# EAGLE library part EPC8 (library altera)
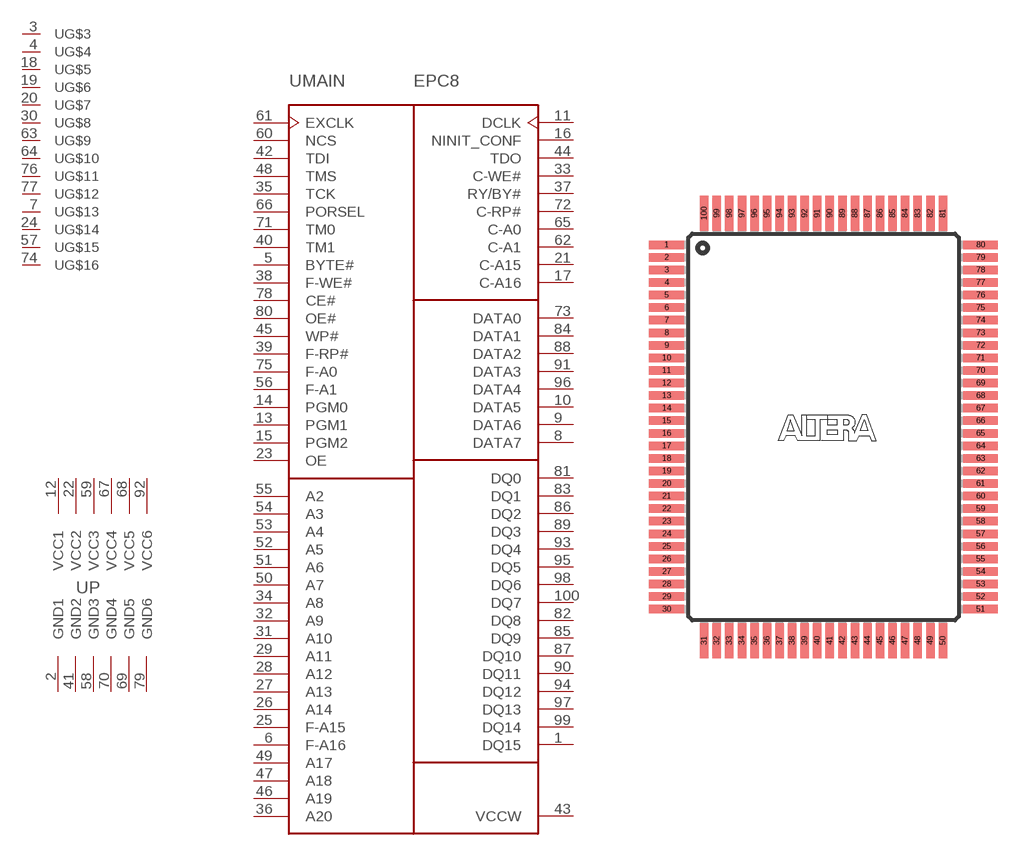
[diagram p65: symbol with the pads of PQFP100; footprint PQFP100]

Designator prefix -; gates MAIN=EPC8 P=EPC8_P G$3=NC G$4=NC G$5=NC G$6=NC G$7=NC G$8=NC G$9=NC G$10=NC G$11=NC G$12=NC G$13=NC G$14=NC G$15=NC G$16=NC

## EPC8  [PQFP100]
1  MAIN:DQ15
2  P:GND1  pwr
3  G$3:NC  nc
4  G$4:NC  nc
5  MAIN:BYTE#  in
6  MAIN:F-A16  in
7  G$13:NC  nc
8  MAIN:DATA7  out
9  MAIN:DATA6  out
10  MAIN:DATA5  out
11  MAIN:DCLK  out
12  P:VCC1  pwr
13  MAIN:PGM1  in
14  MAIN:PGM0  in
15  MAIN:PGM2  in
16  MAIN:NINIT_CONF  out
17  MAIN:C-A16  out
18  G$5:NC  nc
19  G$6:NC  nc
20  G$7:NC  nc
21  MAIN:C-A15  out
22  P:VCC2  pwr
23  MAIN:OE
24  G$14:NC  nc
25  MAIN:F-A15  in
26  MAIN:A14  in
27  MAIN:A13  in
28  MAIN:A12  in
29  MAIN:A11  in
30  G$8:NC  nc
31  MAIN:A10  in
32  MAIN:A9  in
33  MAIN:C-WE#  out
34  MAIN:A8  in
35  MAIN:TCK  in
36  MAIN:A20  in
37  MAIN:RY/BY#  out
38  MAIN:F-WE#  in
39  MAIN:F-RP#  in
40  MAIN:TM1  in
41  P:GND2  pwr
42  MAIN:TDI  in
43  MAIN:VCCW  pwr
44  MAIN:TDO  out
45  MAIN:WP#  in
46  MAIN:A19  in
47  MAIN:A18  in
48  MAIN:TMS  in
49  MAIN:A17  in
50  MAIN:A7  in
51  MAIN:A6  in
52  MAIN:A5  in
53  MAIN:A4  in
54  MAIN:A3  in
55  MAIN:A2  in
56  MAIN:F-A1  in
57  G$15:NC  nc
58  P:GND3  pwr
59  P:VCC3  pwr
60  MAIN:NCS  in
61  MAIN:EXCLK  in
62  MAIN:C-A1  out
63  G$9:NC  nc
64  G$10:NC  nc
65  MAIN:C-A0  out
66  MAIN:PORSEL  in
67  P:VCC4  pwr
68  P:VCC5  pwr
69  P:GND5  pwr
70  P:GND4  pwr
71  MAIN:TM0  in
72  MAIN:C-RP#  out
73  MAIN:DATA0  out
74  G$16:NC  nc
75  MAIN:F-A0  in
76  G$11:NC  nc
77  G$12:NC  nc
78  MAIN:CE#  in
79  P:GND6  pwr
80  MAIN:OE#  in
81  MAIN:DQ0
82  MAIN:DQ8
83  MAIN:DQ1
84  MAIN:DATA1  out
85  MAIN:DQ9
86  MAIN:DQ2
87  MAIN:DQ10
88  MAIN:DATA2  out
89  MAIN:DQ3
90  MAIN:DQ11
91  MAIN:DATA3  out
92  P:VCC6  pwr
93  MAIN:DQ4
94  MAIN:DQ12
95  MAIN:DQ5
96  MAIN:DATA4  out
97  MAIN:DQ13
98  MAIN:DQ6
99  MAIN:DQ14
100  MAIN:DQ7

## Footprint PQFP100 (pad centres in mm)
Plastic Quad Flat Pack
smd 1.8 x 0.44: 1 -8.125,9.425; 2 -8.125,8.775; 3 -8.125,8.125; 4 -8.125,7.475; 5 -8.125,6.825; 6 -8.125,6.175; 7 -8.125,5.525; 8 -8.125,4.875; 9 -8.125,4.225; 10 -8.125,3.575; 11 -8.125,2.925; 12 -8.125,2.275; 13 -8.125,1.625; 14 -8.125,0.975; 15 -8.125,0.325; 16 -8.125,-0.325; 17 -8.125,-0.975; 18 -8.125,-1.625; 19 -8.125,-2.275; 20 -8.125,-2.925; 21 -8.125,-3.575; 22 -8.125,-4.225; 23 -8.125,-4.875; 24 -8.125,-5.525; 25 -8.125,-6.175; 26 -8.125,-6.825; 27 -8.125,-7.475; 28 -8.125,-8.125; 29 -8.125,-8.775; 30 -8.125,-9.425; 51 8.125,-9.425; 52 8.125,-8.775; 53 8.125,-8.125; 54 8.125,-7.475; 55 8.125,-6.825; 56 8.125,-6.175; 57 8.125,-5.525; 58 8.125,-4.875; 59 8.125,-4.225; 60 8.125,-3.575; 61 8.125,-2.925; 62 8.125,-2.275; 63 8.125,-1.625; 64 8.125,-0.975; 65 8.125,-0.325; 66 8.125,0.325; 67 8.125,0.975; 68 8.125,1.625; 69 8.125,2.275; 70 8.125,2.925; 71 8.125,3.575; 72 8.125,4.225; 73 8.125,4.875; 74 8.125,5.525; 75 8.125,6.175; 76 8.125,6.825; 77 8.125,7.475; 78 8.125,8.125; 79 8.125,8.775; 80 8.125,9.425
smd 0.44 x 1.8: 31 -6.175,-11.05; 32 -5.525,-11.05; 33 -4.875,-11.05; 34 -4.225,-11.05; 35 -3.575,-11.05; 36 -2.925,-11.05; 37 -2.275,-11.05; 38 -1.625,-11.05; 39 -0.975,-11.05; 40 -0.325,-11.05; 41 0.325,-11.05; 42 0.975,-11.05; 43 1.625,-11.05; 44 2.275,-11.05; 45 2.925,-11.05; 46 3.575,-11.05; 47 4.225,-11.05; 48 4.875,-11.05; 49 5.525,-11.05; 50 6.175,-11.05; 81 6.175,11.05; 82 5.525,11.05; 83 4.875,11.05; 84 4.225,11.05; 85 3.575,11.05; 86 2.925,11.05; 87 2.275,11.05; 88 1.625,11.05; 89 0.975,11.05; 90 0.325,11.05; 91 -0.325,11.05; 92 -0.975,11.05; 93 -1.625,11.05; 94 -2.275,11.05; 95 -2.925,11.05; 96 -3.575,11.05; 97 -4.225,11.05; 98 -4.875,11.05; 99 -5.525,11.05; 100 -6.175,11.05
